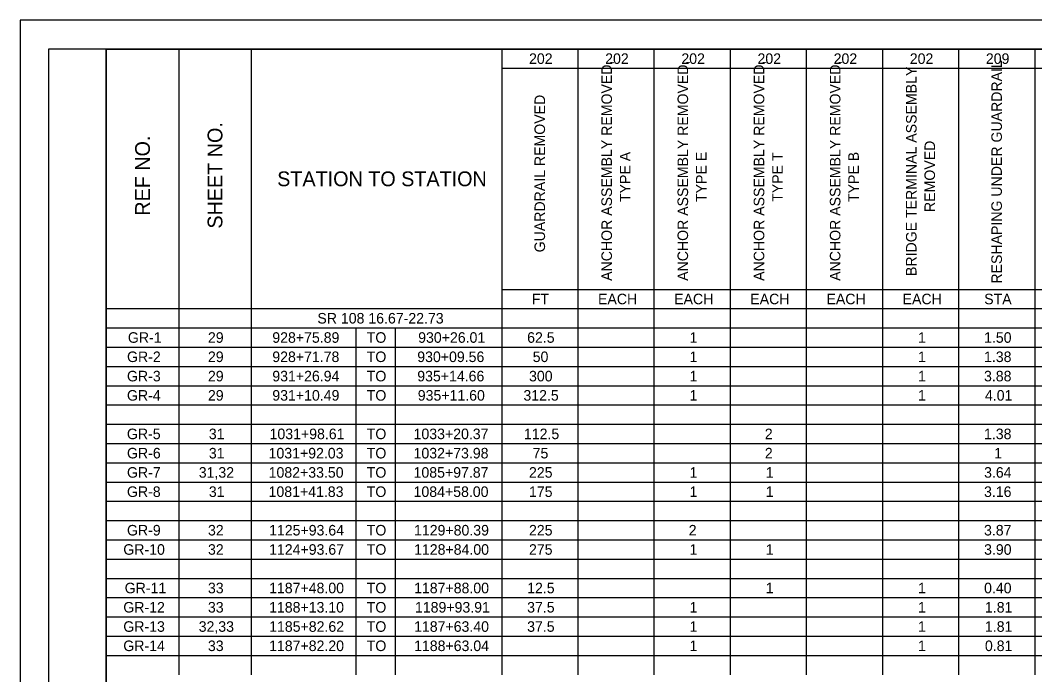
# Model space of a CAD drawing. Extents: x 0 to 34, y 0 to 22.
# Drawn here: x 0 to 17.69, y 10.59 to 22 of the extents above; entities that cross this region are included whole.
import ezdxf

# ---------------------------------------------------------------- set-up
doc = ezdxf.new("R2010")
doc.units = 0
for name, color, linetype in [('SH_Border', 7, 'Continuous'), ('SH_Cut_Line', 7, 'Continuous'), ('SH_Text', 7, 'Continuous')]:
    doc.layers.add(name, color=color, linetype=linetype)

msp = doc.modelspace()

# ---------------------------------------------------------------- linework, layer by layer
at = {"layer": 'SH_Border'}
for points in [[(0.5, 21.5), (1.5, 21.5), (1.5, 0.5), (0.5, 0.5)], [(1.5, 21.5), (33.5, 21.5), (33.5, 0.5), (1.5, 0.5)]]:
    msp.add_lwpolyline(points, close=True, dxfattribs=at)
at = {"layer": 'SH_Cut_Line'}
msp.add_lwpolyline([(0, 0), (34, 0), (34, 22), (0, 22)], close=True, dxfattribs=at)
at = {"layer": 'SH_Text'}
for p, q in [((1.5, 21.499), (2.764, 21.499)), ((1.5, 21.499), (1.5, 21.163)), ((2.764, 21.499), (4.028, 21.499)), ((2.764, 21.499), (2.764, 21.163)), ((4.028, 21.499), (5.853, 21.499)), ((4.028, 21.499), (4.028, 21.163)), ((5.853, 21.499), (8.397, 21.499)), ((8.397, 21.499), (9.725, 21.499)), ((8.397, 21.499), (8.397, 21.163)), ((9.725, 21.499), (13.71, 21.499)), ((9.725, 21.499), (9.725, 21.163)), ((11.053, 21.499), (11.053, 21.163)), ((12.381, 21.499), (12.381, 21.163)), ((13.71, 21.499), (15.038, 21.499)), ((13.71, 21.499), (13.71, 21.163)), ((15.038, 21.499), (17.694, 21.499)), ((15.038, 21.499), (15.038, 21.163)), ((16.366, 21.499), (16.366, 21.163)), ((17.694, 21.499), (19.022, 21.499)), ((17.694, 21.499), (17.694, 21.163)), ((1.5, 21.163), (1.5, 20.827)), ((2.764, 21.163), (2.764, 20.827)), ((4.028, 21.163), (4.028, 20.827)), ((8.397, 21.163), (9.725, 21.163)), ((8.397, 21.163), (8.397, 20.827)), ((9.725, 21.163), (13.71, 21.163)), ((9.725, 21.163), (9.725, 20.827)), ((11.053, 21.163), (11.053, 20.827)), ((12.381, 21.163), (12.381, 20.827)), ((13.71, 21.163), (15.038, 21.163)), ((13.71, 21.163), (13.71, 20.827)), ((15.038, 21.163), (17.694, 21.163)), ((15.038, 21.163), (15.038, 20.827)), ((16.366, 21.163), (16.366, 20.827)), ((17.694, 21.163), (19.022, 21.163)), ((17.694, 21.163), (17.694, 20.827)), ((1.5, 20.827), (1.5, 20.491)), ((2.764, 20.827), (2.764, 20.491)), ((4.028, 20.827), (4.028, 20.491)), ((8.397, 20.827), (8.397, 20.491)), ((9.725, 20.827), (9.725, 20.491)), ((11.053, 20.827), (11.053, 20.491)), ((12.381, 20.827), (12.381, 20.491)), ((13.71, 20.827), (13.71, 20.491)), ((15.038, 20.827), (15.038, 20.491)), ((16.366, 20.827), (16.366, 20.491)), ((17.694, 20.827), (17.694, 20.491)), ((1.5, 20.491), (1.5, 20.155)), ((2.764, 20.491), (2.764, 20.155)), ((4.028, 20.491), (4.028, 20.155)), ((8.397, 20.491), (8.397, 20.155)), ((9.725, 20.491), (9.725, 20.155)), ((11.053, 20.491), (11.053, 20.155)), ((12.381, 20.491), (12.381, 20.155)), ((13.71, 20.491), (13.71, 20.155)), ((15.038, 20.491), (15.038, 20.155)), ((16.366, 20.491), (16.366, 20.155)), ((17.694, 20.491), (17.694, 20.155)), ((1.5, 20.155), (1.5, 19.819)), ((2.764, 20.155), (2.764, 19.819)), ((4.028, 20.155), (4.028, 19.819)), ((8.397, 20.155), (8.397, 19.819)), ((9.725, 20.155), (9.725, 19.819)), ((11.053, 20.155), (11.053, 19.819)), ((12.381, 20.155), (12.381, 19.819)), ((13.71, 20.155), (13.71, 19.819)), ((15.038, 20.155), (15.038, 19.819)), ((16.366, 20.155), (16.366, 19.819)), ((17.694, 20.155), (17.694, 19.819)), ((1.5, 19.819), (1.5, 19.483)), ((2.764, 19.819), (2.764, 19.483)), ((4.028, 19.819), (4.028, 19.483)), ((8.397, 19.819), (8.397, 19.483)), ((9.725, 19.819), (9.725, 19.483)), ((11.053, 19.819), (11.053, 19.483)), ((12.381, 19.819), (12.381, 19.483)), ((13.71, 19.819), (13.71, 19.483)), ((15.038, 19.819), (15.038, 19.483)), ((16.366, 19.819), (16.366, 19.483)), ((17.694, 19.819), (17.694, 19.483)), ((1.5, 19.483), (1.5, 19.147)), ((2.764, 19.483), (2.764, 19.147)), ((4.028, 19.483), (4.028, 19.147)), ((8.397, 19.483), (8.397, 19.147)), ((9.725, 19.483), (9.725, 19.147)), ((11.053, 19.483), (11.053, 19.147)), ((12.381, 19.483), (12.381, 19.147)), ((13.71, 19.483), (13.71, 19.147)), ((15.038, 19.483), (15.038, 19.147)), ((16.366, 19.483), (16.366, 19.147)), ((17.694, 19.483), (17.694, 19.147)), ((1.5, 19.147), (1.5, 18.315)), ((2.764, 19.147), (2.764, 18.315)), ((4.028, 19.147), (4.028, 18.315)), ((8.397, 19.147), (8.397, 18.315)), ((9.725, 19.147), (9.725, 18.315)), ((11.053, 19.147), (11.053, 18.315)), ((12.381, 19.147), (12.381, 18.315)), ((13.71, 19.147), (13.71, 18.315)), ((15.038, 19.147), (15.038, 18.315)), ((16.366, 19.147), (16.366, 18.315)), ((17.694, 19.147), (17.694, 18.315)), ((1.5, 18.315), (1.5, 17.307)), ((2.764, 18.315), (2.764, 17.307)), ((4.028, 18.315), (4.028, 17.307)), ((8.397, 18.315), (8.397, 17.307)), ((9.725, 18.315), (9.725, 17.307)), ((11.053, 18.315), (11.053, 17.307)), ((12.381, 18.315), (12.381, 17.307)), ((13.71, 18.315), (13.71, 17.307)), ((15.038, 18.315), (15.038, 17.307)), ((16.366, 18.315), (16.366, 17.307)), ((17.694, 18.315), (17.694, 17.307)), ((1.5, 17.307), (1.5, 16.971)), ((2.764, 17.307), (2.764, 16.971)), ((4.028, 17.307), (4.028, 16.971)), ((8.397, 17.307), (9.725, 17.307)), ((8.397, 17.307), (8.397, 16.971)), ((9.725, 17.307), (13.71, 17.307)), ((9.725, 17.307), (9.725, 16.971)), ((11.053, 17.307), (11.053, 16.971)), ((12.381, 17.307), (12.381, 16.971)), ((13.71, 17.307), (15.038, 17.307)), ((13.71, 17.307), (13.71, 16.971)), ((15.038, 17.307), (17.694, 17.307)), ((15.038, 17.307), (15.038, 16.971)), ((16.366, 17.307), (16.366, 16.971)), ((17.694, 17.307), (19.022, 17.307)), ((17.694, 17.307), (17.694, 16.971)), ((1.5, 16.971), (2.764, 16.971)), ((1.5, 16.971), (1.5, 16.299)), ((2.764, 16.971), (4.028, 16.971)), ((2.764, 16.971), (2.764, 16.299)), ((4.028, 16.971), (5.853, 16.971)), ((4.028, 16.971), (4.028, 16.299)), ((5.853, 16.971), (8.397, 16.971)), ((8.397, 16.971), (9.725, 16.971)), ((8.397, 16.971), (8.397, 16.299)), ((9.725, 16.971), (13.71, 16.971)), ((9.725, 16.971), (9.725, 16.299)), ((11.053, 16.971), (11.053, 16.299)), ((12.381, 16.971), (12.381, 16.299)), ((13.71, 16.971), (15.038, 16.971)), ((13.71, 16.971), (13.71, 16.299)), ((15.038, 16.971), (17.694, 16.971)), ((15.038, 16.971), (15.038, 16.299)), ((16.366, 16.971), (16.366, 16.299)), ((17.694, 16.971), (19.022, 16.971)), ((17.694, 16.971), (17.694, 16.299)), ((1.5, 16.635), (2.764, 16.635)), ((2.764, 16.635), (4.028, 16.635)), ((4.028, 16.635), (5.853, 16.635)), ((5.853, 16.635), (8.397, 16.635)), ((5.853, 16.635), (5.853, 16.299)), ((6.541, 16.635), (6.541, 16.299)), ((8.397, 16.635), (9.725, 16.635)), ((9.725, 16.635), (13.71, 16.635)), ((13.71, 16.635), (15.038, 16.635)), ((15.038, 16.635), (17.694, 16.635)), ((17.694, 16.635), (19.022, 16.635)), ((1.5, 16.299), (2.764, 16.299)), ((1.5, 16.299), (1.5, 15.962)), ((2.764, 16.299), (4.028, 16.299)), ((2.764, 16.299), (2.764, 15.962)), ((4.028, 16.299), (5.853, 16.299)), ((4.028, 16.299), (4.028, 15.962)), ((5.853, 16.299), (8.397, 16.299)), ((5.853, 16.299), (5.853, 15.962)), ((6.541, 16.299), (6.541, 15.962)), ((8.397, 16.299), (9.725, 16.299)), ((8.397, 16.299), (8.397, 15.962)), ((9.725, 16.299), (13.71, 16.299)), ((9.725, 16.299), (9.725, 15.962)), ((11.053, 16.299), (11.053, 15.962)), ((12.381, 16.299), (12.381, 15.962)), ((13.71, 16.299), (15.038, 16.299)), ((13.71, 16.299), (13.71, 15.962)), ((15.038, 16.299), (17.694, 16.299)), ((15.038, 16.299), (15.038, 15.962)), ((16.366, 16.299), (16.366, 15.962)), ((17.694, 16.299), (19.022, 16.299)), ((17.694, 16.299), (17.694, 15.962)), ((1.5, 15.962), (2.764, 15.962)), ((1.5, 15.962), (1.5, 14.282)), ((2.764, 15.962), (4.028, 15.962)), ((2.764, 15.962), (2.764, 14.282)), ((4.028, 15.962), (5.853, 15.962)), ((4.028, 15.962), (4.028, 14.282)), ((5.853, 15.962), (8.397, 15.962)), ((5.853, 15.962), (5.853, 14.282)), ((6.541, 15.962), (6.541, 14.282)), ((8.397, 15.962), (9.725, 15.962)), ((8.397, 15.962), (8.397, 14.282)), ((9.725, 15.962), (13.71, 15.962)), ((9.725, 15.962), (9.725, 14.282)), ((11.053, 15.962), (11.053, 14.282)), ((12.381, 15.962), (12.381, 14.282)), ((13.71, 15.962), (15.038, 15.962)), ((13.71, 15.962), (13.71, 14.282)), ((15.038, 15.962), (17.694, 15.962)), ((15.038, 15.962), (15.038, 14.282)), ((16.366, 15.962), (16.366, 14.282)), ((17.694, 15.962), (19.022, 15.962)), ((17.694, 15.962), (17.694, 14.282)), ((1.5, 15.626), (2.764, 15.626)), ((2.764, 15.626), (4.028, 15.626)), ((4.028, 15.626), (5.853, 15.626)), ((5.853, 15.626), (8.397, 15.626)), ((8.397, 15.626), (9.725, 15.626)), ((9.725, 15.626), (13.71, 15.626)), ((13.71, 15.626), (15.038, 15.626)), ((15.038, 15.626), (17.694, 15.626)), ((17.694, 15.626), (19.022, 15.626)), ((1.5, 15.29), (2.764, 15.29)), ((2.764, 15.29), (4.028, 15.29)), ((4.028, 15.29), (5.853, 15.29)), ((5.853, 15.29), (8.397, 15.29)), ((8.397, 15.29), (9.725, 15.29)), ((9.725, 15.29), (13.71, 15.29)), ((13.71, 15.29), (15.038, 15.29)), ((15.038, 15.29), (17.694, 15.29)), ((17.694, 15.29), (19.022, 15.29)), ((1.5, 14.954), (2.764, 14.954)), ((2.764, 14.954), (4.028, 14.954)), ((4.028, 14.954), (5.853, 14.954)), ((5.853, 14.954), (8.397, 14.954)), ((8.397, 14.954), (9.725, 14.954)), ((9.725, 14.954), (13.71, 14.954)), ((13.71, 14.954), (15.038, 14.954)), ((15.038, 14.954), (17.694, 14.954)), ((17.694, 14.954), (19.022, 14.954)), ((1.5, 14.618), (2.764, 14.618)), ((2.764, 14.618), (4.028, 14.618)), ((4.028, 14.618), (5.853, 14.618)), ((5.853, 14.618), (8.397, 14.618)), ((8.397, 14.618), (9.725, 14.618)), ((9.725, 14.618), (13.71, 14.618)), ((13.71, 14.618), (15.038, 14.618)), ((15.038, 14.618), (17.694, 14.618)), ((17.694, 14.618), (19.022, 14.618)), ((1.5, 14.282), (2.764, 14.282)), ((1.5, 14.282), (1.5, 13.61)), ((2.764, 14.282), (4.028, 14.282)), ((2.764, 14.282), (2.764, 13.61)), ((4.028, 14.282), (5.853, 14.282)), ((4.028, 14.282), (4.028, 13.61)), ((5.853, 14.282), (8.397, 14.282)), ((5.853, 14.282), (5.853, 13.61)), ((6.541, 14.282), (6.541, 13.61)), ((8.397, 14.282), (9.725, 14.282)), ((8.397, 14.282), (8.397, 13.61)), ((9.725, 14.282), (13.71, 14.282)), ((9.725, 14.282), (9.725, 13.61)), ((11.053, 14.282), (11.053, 13.61)), ((12.381, 14.282), (12.381, 13.61)), ((13.71, 14.282), (15.038, 14.282)), ((13.71, 14.282), (13.71, 13.61)), ((15.038, 14.282), (17.694, 14.282)), ((15.038, 14.282), (15.038, 13.61)), ((16.366, 14.282), (16.366, 13.61)), ((17.694, 14.282), (19.022, 14.282)), ((17.694, 14.282), (17.694, 13.61)), ((1.5, 13.946), (2.764, 13.946)), ((2.764, 13.946), (4.028, 13.946)), ((4.028, 13.946), (5.853, 13.946)), ((5.853, 13.946), (8.397, 13.946)), ((8.397, 13.946), (9.725, 13.946)), ((9.725, 13.946), (13.71, 13.946)), ((13.71, 13.946), (15.038, 13.946)), ((15.038, 13.946), (17.694, 13.946)), ((17.694, 13.946), (19.022, 13.946)), ((1.5, 13.61), (2.764, 13.61)), ((1.5, 13.61), (1.5, 12.938)), ((2.764, 13.61), (4.028, 13.61)), ((2.764, 13.61), (2.764, 12.938)), ((4.028, 13.61), (5.853, 13.61)), ((4.028, 13.61), (4.028, 12.938)), ((5.853, 13.61), (8.397, 13.61)), ((5.853, 13.61), (5.853, 12.938)), ((6.541, 13.61), (6.541, 12.938)), ((8.397, 13.61), (9.725, 13.61)), ((8.397, 13.61), (8.397, 12.938)), ((9.725, 13.61), (13.71, 13.61)), ((9.725, 13.61), (9.725, 12.938)), ((11.053, 13.61), (11.053, 12.938)), ((12.381, 13.61), (12.381, 12.938)), ((13.71, 13.61), (15.038, 13.61)), ((13.71, 13.61), (13.71, 12.938)), ((15.038, 13.61), (17.694, 13.61)), ((15.038, 13.61), (15.038, 12.938)), ((16.366, 13.61), (16.366, 12.938)), ((17.694, 13.61), (19.022, 13.61)), ((17.694, 13.61), (17.694, 12.938)), ((1.5, 13.274), (2.764, 13.274)), ((2.764, 13.274), (4.028, 13.274)), ((4.028, 13.274), (5.853, 13.274)), ((5.853, 13.274), (8.397, 13.274)), ((8.397, 13.274), (9.725, 13.274)), ((9.725, 13.274), (13.71, 13.274)), ((13.71, 13.274), (15.038, 13.274)), ((15.038, 13.274), (17.694, 13.274)), ((17.694, 13.274), (19.022, 13.274)), ((1.5, 12.938), (2.764, 12.938)), ((1.5, 12.938), (1.5, 12.602)), ((2.764, 12.938), (4.028, 12.938)), ((2.764, 12.938), (2.764, 12.602)), ((4.028, 12.938), (5.853, 12.938)), ((4.028, 12.938), (4.028, 12.602)), ((5.853, 12.938), (8.397, 12.938)), ((5.853, 12.938), (5.853, 12.602)), ((6.541, 12.938), (6.541, 12.602)), ((8.397, 12.938), (9.725, 12.938)), ((8.397, 12.938), (8.397, 12.602)), ((9.725, 12.938), (13.71, 12.938)), ((9.725, 12.938), (9.725, 12.602)), ((11.053, 12.938), (11.053, 12.602)), ((12.381, 12.938), (12.381, 12.602)), ((13.71, 12.938), (15.038, 12.938)), ((13.71, 12.938), (13.71, 12.602)), ((15.038, 12.938), (17.694, 12.938)), ((15.038, 12.938), (15.038, 12.602)), ((16.366, 12.938), (16.366, 12.602)), ((17.694, 12.938), (19.022, 12.938)), ((17.694, 12.938), (17.694, 12.602)), ((1.5, 12.602), (2.764, 12.602)), ((1.5, 12.602), (1.5, 11.93)), ((2.764, 12.602), (4.028, 12.602)), ((2.764, 12.602), (2.764, 11.93)), ((4.028, 12.602), (5.853, 12.602)), ((4.028, 12.602), (4.028, 11.93)), ((5.853, 12.602), (8.397, 12.602)), ((5.853, 12.602), (5.853, 11.93)), ((6.541, 12.602), (6.541, 11.93)), ((8.397, 12.602), (9.725, 12.602)), ((8.397, 12.602), (8.397, 11.93)), ((9.725, 12.602), (13.71, 12.602)), ((9.725, 12.602), (9.725, 11.93)), ((11.053, 12.602), (11.053, 11.93)), ((12.381, 12.602), (12.381, 11.93)), ((13.71, 12.602), (15.038, 12.602)), ((13.71, 12.602), (13.71, 11.93)), ((15.038, 12.602), (17.694, 12.602)), ((15.038, 12.602), (15.038, 11.93)), ((16.366, 12.602), (16.366, 11.93)), ((17.694, 12.602), (19.022, 12.602)), ((17.694, 12.602), (17.694, 11.93)), ((1.5, 12.266), (2.764, 12.266)), ((2.764, 12.266), (4.028, 12.266)), ((4.028, 12.266), (5.853, 12.266)), ((5.853, 12.266), (8.397, 12.266)), ((8.397, 12.266), (9.725, 12.266)), ((9.725, 12.266), (13.71, 12.266)), ((13.71, 12.266), (15.038, 12.266)), ((15.038, 12.266), (17.694, 12.266)), ((17.694, 12.266), (19.022, 12.266)), ((1.5, 11.93), (2.764, 11.93)), ((1.5, 11.93), (1.5, 11.594)), ((2.764, 11.93), (4.028, 11.93)), ((2.764, 11.93), (2.764, 11.594)), ((4.028, 11.93), (5.853, 11.93)), ((4.028, 11.93), (4.028, 11.594)), ((5.853, 11.93), (8.397, 11.93)), ((5.853, 11.93), (5.853, 11.594)), ((6.541, 11.93), (6.541, 11.594)), ((8.397, 11.93), (9.725, 11.93)), ((8.397, 11.93), (8.397, 11.594)), ((9.725, 11.93), (13.71, 11.93)), ((9.725, 11.93), (9.725, 11.594)), ((11.053, 11.93), (11.053, 11.594)), ((12.381, 11.93), (12.381, 11.594)), ((13.71, 11.93), (15.038, 11.93)), ((13.71, 11.93), (13.71, 11.594)), ((15.038, 11.93), (17.694, 11.93)), ((15.038, 11.93), (15.038, 11.594)), ((16.366, 11.93), (16.366, 11.594)), ((17.694, 11.93), (19.022, 11.93)), ((17.694, 11.93), (17.694, 11.594)), ((1.5, 11.594), (2.764, 11.594)), ((1.5, 11.594), (1.5, 10.586)), ((2.764, 11.594), (4.028, 11.594)), ((2.764, 11.594), (2.764, 10.586)), ((4.028, 11.594), (5.853, 11.594)), ((4.028, 11.594), (4.028, 10.586)), ((5.853, 11.594), (8.397, 11.594)), ((5.853, 11.594), (5.853, 10.586)), ((6.541, 11.594), (6.541, 10.586)), ((8.397, 11.594), (9.725, 11.594)), ((8.397, 11.594), (8.397, 10.586)), ((9.725, 11.594), (13.71, 11.594)), ((9.725, 11.594), (9.725, 10.586)), ((11.053, 11.594), (11.053, 10.586)), ((12.381, 11.594), (12.381, 10.586)), ((13.71, 11.594), (15.038, 11.594)), ((13.71, 11.594), (13.71, 10.586)), ((15.038, 11.594), (17.694, 11.594)), ((15.038, 11.594), (15.038, 10.586)), ((16.366, 11.594), (16.366, 10.586)), ((17.694, 11.594), (19.022, 11.594)), ((17.694, 11.594), (17.694, 10.586)), ((1.5, 11.258), (2.764, 11.258)), ((2.764, 11.258), (4.028, 11.258)), ((4.028, 11.258), (5.853, 11.258)), ((5.853, 11.258), (8.397, 11.258)), ((8.397, 11.258), (9.725, 11.258)), ((9.725, 11.258), (13.71, 11.258)), ((13.71, 11.258), (15.038, 11.258)), ((15.038, 11.258), (17.694, 11.258)), ((17.694, 11.258), (19.022, 11.258)), ((1.5, 10.922), (2.764, 10.922)), ((2.764, 10.922), (4.028, 10.922)), ((4.028, 10.922), (5.853, 10.922)), ((5.853, 10.922), (8.397, 10.922)), ((8.397, 10.922), (9.725, 10.922)), ((9.725, 10.922), (13.71, 10.922)), ((13.71, 10.922), (15.038, 10.922)), ((15.038, 10.922), (17.694, 10.922)), ((17.694, 10.922), (19.022, 10.922))]:
    msp.add_line(p, q, dxfattribs=at)

# ---------------------------------------------------------------- texts
for s, height, p in [('202', 0.184, (8.874, 21.239)), ('202', 0.184, (10.202, 21.239)), ('202', 0.184, (11.531, 21.239)), ('202', 0.184, (12.859, 21.239)), ('202', 0.184, (14.187, 21.239)), ('202', 0.184, (15.515, 21.239)), ('209', 0.184, (16.842, 21.239)), ('STATION TO STATION', 0.25763, (4.481, 19.106)), ('FT', 0.184, (8.922, 17.047)), ('EACH', 0.184, (10.077, 17.047)), ('EACH', 0.184, (11.405, 17.047)), ('EACH', 0.184, (12.733, 17.047)), ('EACH', 0.184, (14.062, 17.047)), ('EACH', 0.184, (15.39, 17.047)), ('STA', 0.184, (16.813, 17.047)), ('SR 108 16.67-22.73', 0.18402, (5.182, 16.711)), ('GR-1', 0.184, (1.877, 16.375)), ('29', 0.184, (3.273, 16.375)), ('928+75.89', 0.184, (4.396, 16.375)), ('TO', 0.184, (6.043, 16.375)), ('930+26.01', 0.184, (6.94, 16.375)), ('62.5', 0.184, (8.841, 16.375)), ('1', 0.184, (11.674, 16.375)), ('1', 0.184, (15.659, 16.375)), ('1.50', 0.184, (16.811, 16.375)), ('GR-2', 0.184, (1.862, 16.039)), ('29', 0.184, (3.273, 16.039)), ('928+71.78', 0.184, (4.396, 16.039)), ('TO', 0.184, (6.043, 16.039)), ('930+09.56', 0.184, (6.924, 16.039)), ('50', 0.184, (8.938, 16.039)), ('1', 0.184, (11.674, 16.039)), ('1', 0.184, (15.659, 16.039)), ('1.38', 0.184, (16.81, 16.039)), ('GR-3', 0.184, (1.861, 15.702)), ('29', 0.184, (3.273, 15.702)), ('931+26.94', 0.184, (4.396, 15.702)), ('TO', 0.184, (6.043, 15.702)), ('935+14.66', 0.184, (6.924, 15.702)), ('300', 0.184, (8.874, 15.702)), ('1', 0.184, (11.674, 15.702)), ('1', 0.184, (15.659, 15.702)), ('3.88', 0.184, (16.81, 15.702)), ('GR-4', 0.184, (1.861, 15.366)), ('29', 0.184, (3.273, 15.366)), ('931+10.49', 0.184, (4.396, 15.366)), ('TO', 0.184, (6.043, 15.366)), ('935+11.60', 0.184, (6.933, 15.366)), ('312.5', 0.184, (8.776, 15.366)), ('1', 0.184, (11.674, 15.366)), ('1', 0.184, (15.659, 15.366)), ('4.01', 0.184, (16.826, 15.366)), ('GR-5', 0.184, (1.86, 14.694)), ('31', 0.184, (3.289, 14.694)), ('1031+98.61', 0.184, (4.348, 14.694)), ('TO', 0.184, (6.043, 14.694)), ('1033+20.37', 0.184, (6.86, 14.694)), ('112.5', 0.184, (8.785, 14.694)), ('2', 0.184, (12.987, 14.694)), ('1.38', 0.184, (16.81, 14.694)), ('GR-6', 0.184, (1.861, 14.358)), ('31', 0.184, (3.289, 14.358)), ('1031+92.03', 0.184, (4.331, 14.358)), ('TO', 0.184, (6.043, 14.358)), ('1032+73.98', 0.184, (6.86, 14.358)), ('75', 0.184, (8.937, 14.358)), ('2', 0.184, (12.987, 14.358)), ('1', 0.184, (16.987, 14.358)), ('GR-7', 0.184, (1.861, 14.022)), ('31,32', 0.184, (3.113, 14.022)), ('1082+33.50', 0.184, (4.332, 14.022)), ('TO', 0.184, (6.043, 14.022)), ('1085+97.87', 0.184, (6.86, 14.022)), ('225', 0.184, (8.873, 14.022)), ('1', 0.184, (11.674, 14.022)), ('1', 0.184, (13.002, 14.022)), ('3.64', 0.184, (16.811, 14.022)), ('GR-8', 0.184, (1.861, 13.686)), ('31', 0.184, (3.289, 13.686)), ('1081+41.83', 0.184, (4.331, 13.686)), ('TO', 0.184, (6.043, 13.686)), ('1084+58.00', 0.184, (6.86, 13.686)), ('175', 0.184, (8.873, 13.686)), ('1', 0.184, (11.674, 13.686)), ('1', 0.184, (13.002, 13.686)), ('3.16', 0.184, (16.81, 13.686)), ('GR-9', 0.184, (1.861, 13.014)), ('32', 0.184, (3.274, 13.014)), ('1125+93.64', 0.184, (4.34, 13.014)), ('TO', 0.184, (6.043, 13.014)), ('1129+80.39', 0.184, (6.868, 13.014)), ('225', 0.184, (8.873, 13.014)), ('2', 0.184, (11.659, 13.014)), ('3.87', 0.184, (16.81, 13.014)), ('GR-10', 0.184, (1.797, 12.678)), ('32', 0.184, (3.274, 12.678)), ('1124+93.67', 0.184, (4.34, 12.678)), ('TO', 0.184, (6.043, 12.678)), ('1128+84.00', 0.184, (6.869, 12.678)), ('275', 0.184, (8.873, 12.678)), ('1', 0.184, (11.674, 12.678)), ('1', 0.184, (13.002, 12.678)), ('3.90', 0.184, (16.811, 12.678)), ('GR-11', 0.184, (1.821, 12.006)), ('33', 0.184, (3.273, 12.006)), ('1187+48.00', 0.184, (4.34, 12.006)), ('TO', 0.184, (6.043, 12.006)), ('1187+88.00', 0.184, (6.869, 12.006)), ('12.5', 0.184, (8.841, 12.006)), ('1', 0.184, (13.002, 12.006)), ('1', 0.184, (15.659, 12.006)), ('0.40', 0.184, (16.811, 12.006)), ('GR-12', 0.184, (1.797, 11.67)), ('33', 0.184, (3.273, 11.67)), ('1188+13.10', 0.184, (4.34, 11.67)), ('TO', 0.184, (6.043, 11.67)), ('1189+93.91', 0.184, (6.884, 11.67)), ('37.5', 0.184, (8.841, 11.67)), ('1.81', 0.184, (16.826, 11.67)), ('1', 0.184, (11.674, 11.67)), ('1', 0.184, (15.659, 11.67)), ('GR-13', 0.184, (1.797, 11.334)), ('32,33', 0.184, (3.112, 11.334)), ('1185+82.62', 0.184, (4.341, 11.334)), ('TO', 0.184, (6.043, 11.334)), ('1187+63.40', 0.184, (6.869, 11.334)), ('37.5', 0.184, (8.841, 11.334)), ('1', 0.184, (11.674, 11.334)), ('1', 0.184, (15.659, 11.334)), ('1.81', 0.184, (16.826, 11.334)), ('GR-14', 0.184, (1.797, 10.998)), ('33', 0.184, (3.273, 10.998)), ('1187+82.20', 0.184, (4.34, 10.998)), ('TO', 0.184, (6.043, 10.998)), ('1188+63.04', 0.184, (6.869, 10.998)), ('1', 0.184, (11.674, 10.998)), ('1', 0.184, (15.659, 10.998)), ('0.81', 0.184, (16.826, 10.998))]:
    msp.add_text(s, height=height, dxfattribs=at).set_placement(p)
for s, height, p in [('ANCHOR ASSEMBLY REMOVED, ', 0.18402, (10.32, 17.455)), ('ANCHOR ASSEMBLY REMOVED, ', 0.18402, (11.648, 17.455)), ('ANCHOR ASSEMBLY REMOVED, ', 0.18402, (12.977, 17.455)), ('ANCHOR ASSEMBLY REMOVED, ', 0.18402, (14.305, 17.455)), ('RESHAPING UNDER GUARDRAIL', 0.18402, (17.122, 17.407)), ('BRIDGE TERMINAL ASSEMBLY ', 0.18402, (15.633, 17.54)), ('GUARDRAIL REMOVED', 0.18402, (9.153, 17.953)), ('SHEET NO.', 0.2576, (3.525, 18.367)), ('REF NO.', 0.2576, (2.261, 18.592)), ('REMOVED', 0.184, (15.955, 18.656)), ('TYPE A', 0.184, (10.642, 18.83)), ('TYPE E', 0.184, (11.97, 18.83)), ('TYPE T', 0.184, (13.299, 18.834)), ('TYPE B', 0.184, (14.627, 18.83))]:
    msp.add_text(s, height=height, rotation=90, dxfattribs=at).set_placement(p)

doc.saveas('drawing.dxf')
